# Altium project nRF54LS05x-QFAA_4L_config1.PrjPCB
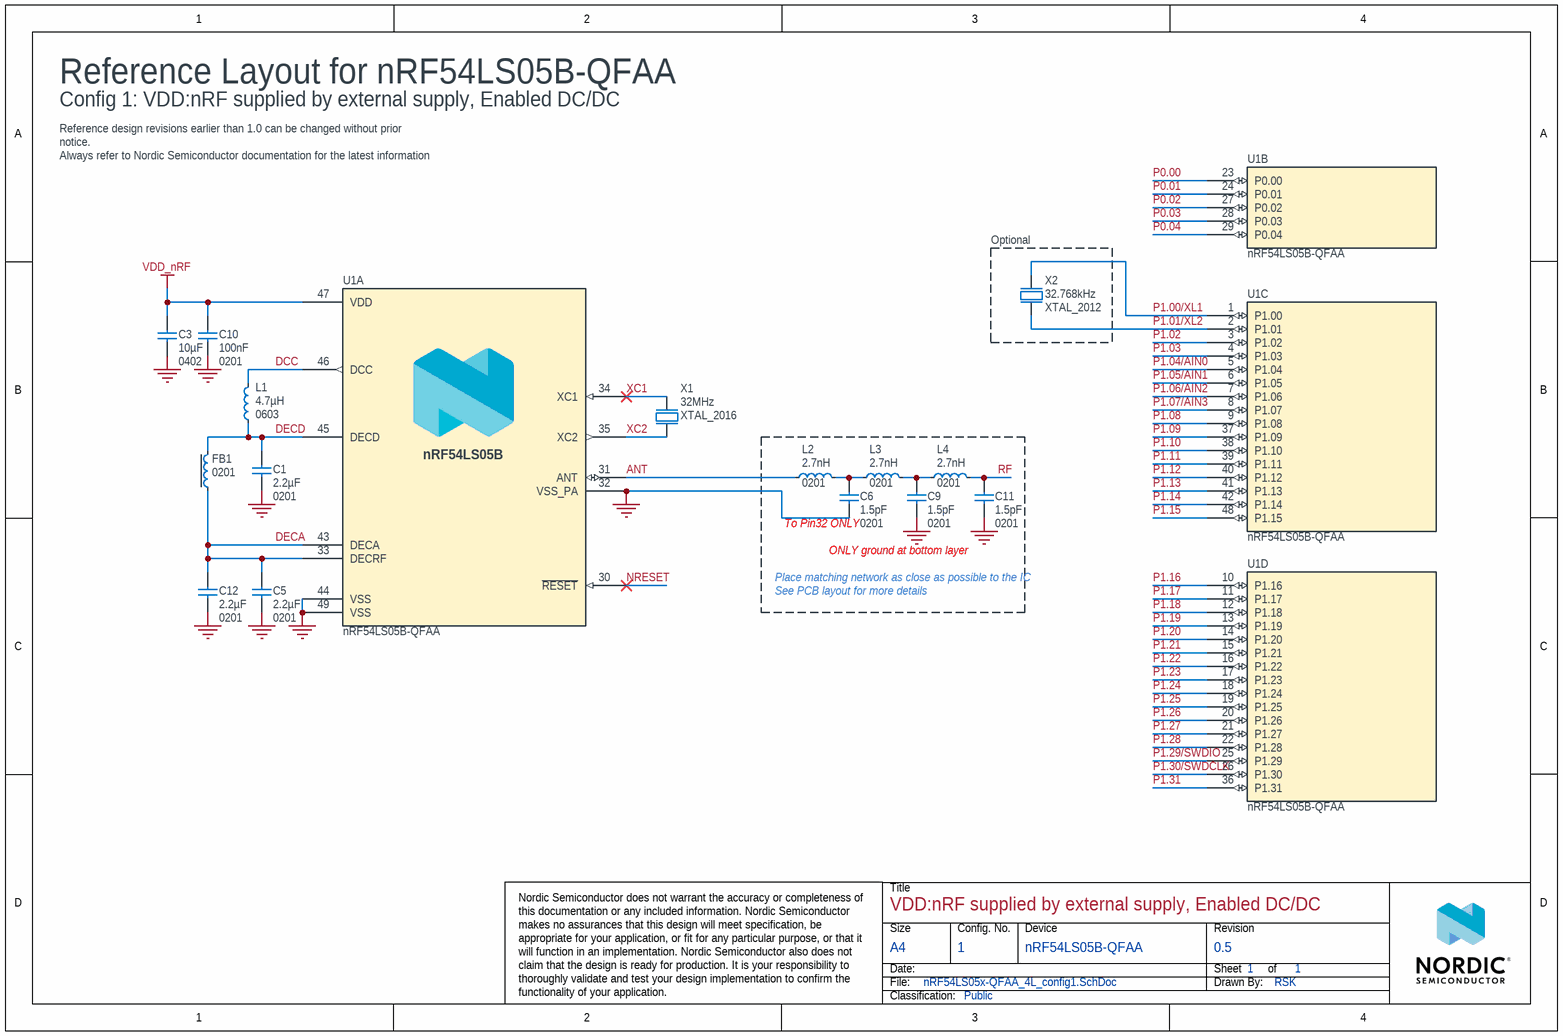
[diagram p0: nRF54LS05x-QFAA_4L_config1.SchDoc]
Classification: Public; Config: 1; Device: nRF54LS05B-QFAA; DrawnBy: RSK; RefLayoutTitle: VDD:nRF supplied by external supply, Enabled DC/DC; Revision: 0.5
1 sheet, 16 parts. Net scope: global (net labels, ports and power ports of the same name join across sheets).
Board file: nRF54LS05x-QFAA_4L_config1.PcbDoc

## Sheet nRF54LS05x-QFAA_4L_config1.SchDoc
size A4; Organization: Nordic Semiconductor; SheetNumber: 1; SheetTotal: 1; DocumentSize: A4

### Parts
C1  2.2µF  Footprint Doc: 0201  [CAPC0603X03L_C]
C3  10µF  Footprint Doc: 0402  [CAPC1005X04L]
C5  Footprint Doc: 0201  [CAPC0603X03L_C]  (hidden comment: 2.2µF)
C6  1.5pF  Footprint Doc: 0201  [CAPC0603X03L_C]
C9  1.5pF  Footprint Doc: 0201  [CAPC0603X03L_C]
C10  100nF  Footprint Doc: 0201  [CAPC0603X03L_C]
C11  1.5pF  Footprint Doc: 0201  [CAPC0603X03L_C]
C12  Footprint Doc: 0201  [CAPC0603X03L_C]  (hidden comment: 2.2µF)
FB1  Footprint Doc: 0201  [INDC0603X03L_C]  (hidden comment: 120R/0.2A)
L1  4.7µH  Footprint Doc: 0603  [INDC1608X06L]
L2  2.7nH  Footprint Doc: 0201  [INDC0603X03L_C]
L3  2.7nH  Footprint Doc: 0201  [INDC0603X03L_C]
L4  2.7nH  Footprint Doc: 0201  [INDC0603X03L_C]
U1  nRF54LS05B-QFAA  [QFN49P40_600x600x90L40x20T460N]  (parts A,B,C,D of 4)
X1  32MHz  Footprint Doc: XTAL_2016  [BT-XTAL_2016]
X2  32.768kHz  [XTAL_2012]

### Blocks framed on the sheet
Optional: X2

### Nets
GND: C1.1 C3.1 C5.1 C6.1 C9.1 C10.1 C11.1 C12.1 U1.32(VSS_PA) U1.44(VSS) U1.49(VSS) X1.2(GND) X1.4(GND)
VDD_nRF: C3.2 C10.2 U1.47(VDD)
ANT: L2.1 U1.31(ANT)
DCC: L1.1 U1.46(DCC)
DECA: C5.2 C12.2 FB1.2 U1.33(DECRF) U1.43(DECA)
DECD: C1.2 FB1.1 L1.2 U1.45(DECD)
NRESET: U1.30(~{RESET})
P0.00: U1.23(P0.00)
P0.01: U1.24(P0.01)
P0.02: U1.27(P0.02)
P0.03: U1.28(P0.03)
P0.04: U1.29(P0.04)
P1.00/XL1: U1.1(P1.00) X2.2(out)
P1.01/XL2: U1.2(P1.01) X2.1(inp)
P1.02: U1.3(P1.02)
P1.03: U1.4(P1.03)
P1.04/AIN0: U1.5(P1.04)
P1.05/AIN1: U1.6(P1.05)
P1.06/AIN2: U1.7(P1.06)
P1.07/AIN3: U1.8(P1.07)
P1.08: U1.9(P1.08)
P1.09: U1.37(P1.09)
P1.10: U1.38(P1.10)
P1.11: U1.39(P1.11)
P1.12: U1.40(P1.12)
P1.13: U1.41(P1.13)
P1.14: U1.42(P1.14)
P1.15: U1.48(P1.15)
P1.16: U1.10(P1.16)
P1.17: U1.11(P1.17)
P1.18: U1.12(P1.18)
P1.19: U1.13(P1.19)
P1.20: U1.14(P1.20)
P1.21: U1.15(P1.21)
P1.22: U1.16(P1.22)
P1.23: U1.17(P1.23)
P1.24: U1.18(P1.24)
P1.25: U1.19(P1.25)
P1.26: U1.20(P1.26)
P1.27: U1.21(P1.27)
P1.28: U1.22(P1.28)
P1.29/SWDIO: U1.25(P1.29)
P1.30/SWDCLK: U1.26(P1.30)
P1.31: U1.36(P1.31)
RF: C11.2 L4.2
XC1: U1.34(XC1) X1.1(inp)
XC2: U1.35(XC2) X1.3(out)
NetC6_2: C6.2 L2.2 L3.1
NetC9_2: C9.2 L3.2 L4.1

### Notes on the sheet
- Place matching network as close as possible to the IC
- (near C6) To Pin32 ONLY
- ONLY ground at bottom layer
- See PCB layout for more details

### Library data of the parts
C1 C5 C12 = C0201-2µ2-2.5V-X6T-GRM033D80E225ME47D: Capacitor, Ceramic, 2.2µF 2.5V X6T 0201,±20%; Manufacturer: Murata; Part number NEMS: 100200527; Component Status: Active; Pad Count: 2; Note: 2.5V, 20%, X6T; Artikkelnr Noca: N.A.
C3 = C0402-10µF-6.3V-X6S: Capacitor, X6S, ±20%, 6.3V; Manufacturer: N.A.; Part number NEMS: 100200478; Component Status: Active; Pad Count: 2
C6 C9 C11 = C0201-1.5p-25V-NP0-GJM0335C1E1R5WB01: Capacitor, NP0, ±0.05pF, 25V, High Q; Manufacturer: Murata; Part number NEMS: 100200477; Component Status: Active; Pad Count: 2; Artikkelnr Noca: N.A.
C10 = C0201-100n-10V-X7R: Capacitor, X7R, ±10%, 10V; Manufacturer: N.A.; Part number NEMS: 100200469; Pad Count: 2; Component Status: Active
FB1 = FB0201-120R@100M-200mA-BLM03AG121SN1D: Ferrite Bead, 120 Ohm @ 100MHz, 200mA, 500 mOhm Max; Manufacturer: Murata; Part number NEMS: 100300419; Component Status: Active; Pad Count: 2; Artikkelnr Noca: N.A.
L1 = L0603-4µ7-MLZ1608M4R7WT000: Inductor, 120mA, ±20%, 0.65R; Manufacturer: TDK Corporation; Part number NEMS: 100300440; Component Status: Active; Pad Count: 2; Note: Power Inductor ±20%; Artikkelnr Noca: N.A.
L2-L4 = L0201-2n7-HQ-Murata: Inductor, 600mA, ±0.1ｎH, 120mOhm; Manufacturer: Murata; Manufacturer Part Number: LQP03HQ2N7B02; Part number IPS: 00000001753; Part number NEMS: 100300214; Component Status: Active; Pad Count: 2; Note: -55°C ~ 125°C; Artikkelnr Noca: N.A.
U1 = nRF54LS05B-QFAA: Ultra-low-power Bluetooth LE SoC with 508 KB NVM and 96 KB  RAM, supporting Bluetooth LE and 2.4 GHz proprietary protocols; Manufacturer: Nordic Semiconductor; Part number NEMS: 102000422; Component Status: Active; Pad Count: 49; Note: N.A.
X1 = XTAL_SMD2016_32MHz_8pF_Kyocera: XTAL SMD 2016, 32MHz, Cl=8pF, Tot: ±40ppm; Manufacturer Part Number: CX2016DB32000D0WZRC1; Part number IPS: 00000007827; Part number Norautron: 26511136; Part number NEMS: 101600039; Component Status: Active; Pad Count: 4; Note: XTAL SMD 32.000MHz; Artikkelnr Noca: 22010022
X2 = XTAL_SMD2012_32.768kHz_9pF_TXC: XTAL SMD 2012, 32.768kHz, 9pF, ±20ppm; Manufacturer: TXC Corporation; Manufacturer Part Number: 9HT11-32.768KDZC-T; Part number NEMS: 101600107; Component Status: Active; Pad Count: 2; Note: XTAL SMD 32.768kHz; Artikkelnr Noca: N.A.

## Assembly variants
default: all parts fitted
